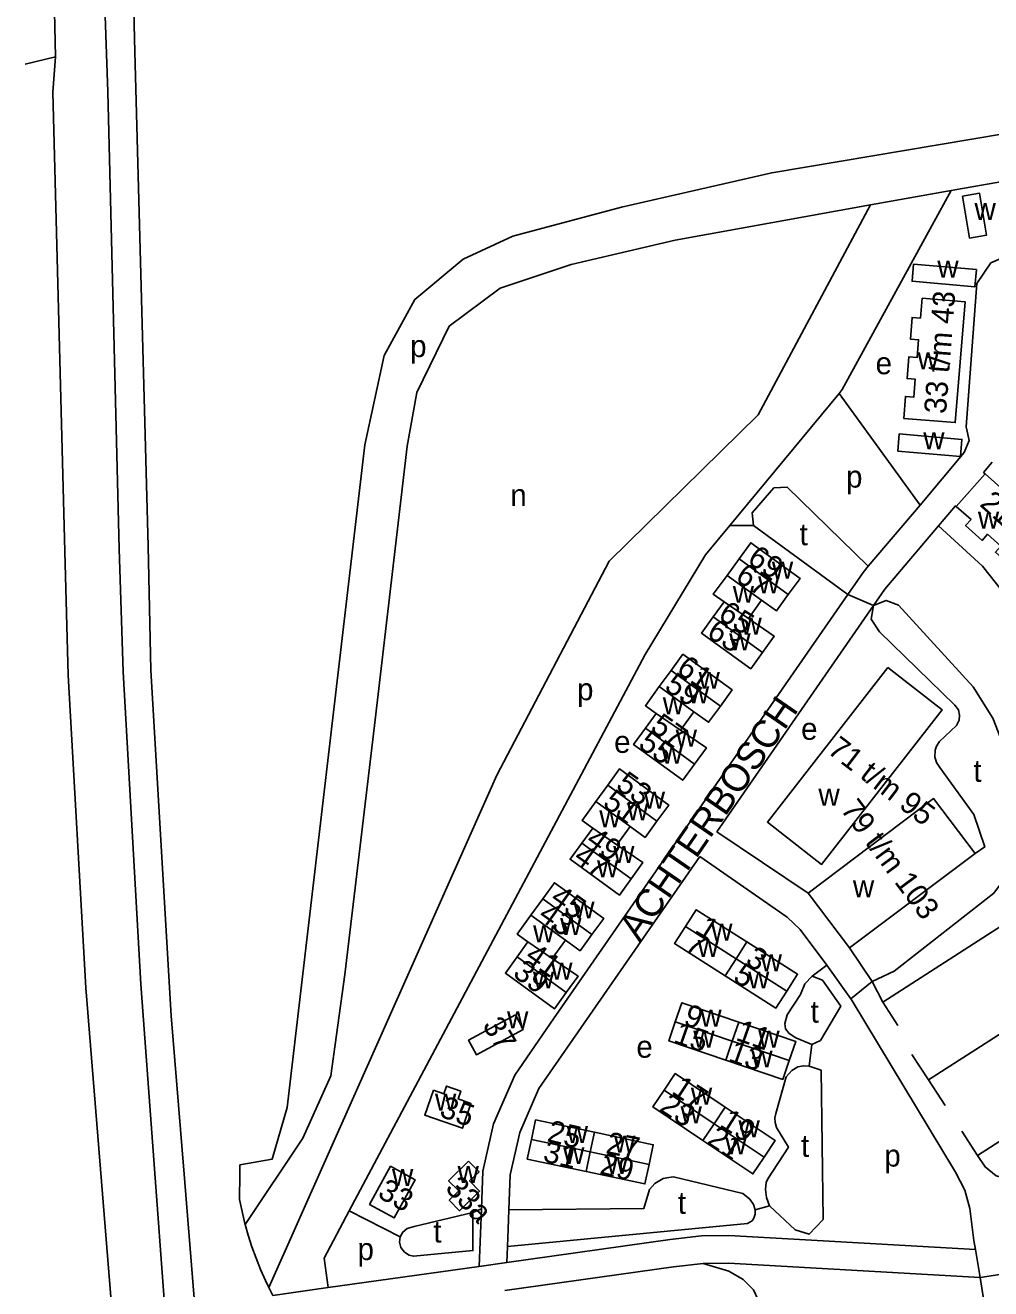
# Model space of a CAD drawing. Extents: x 159441 to 162086, y 388175 to 389787.
# Drawn here: x 159441.2 to 159616.2, y 389297.7 to 389526.7 of the extents above; entities that cross this region are included whole.
import ezdxf

# ---------------------------------------------------------------- set-up
doc = ezdxf.new("R2010")
doc.units = 0
for name, color, linetype in [('BLT_Basislijn', 7, 'Continuous'), ('BLT_Bebouwing', 7, 'Continuous'), ('BLT_Centroide', 7, 'Continuous'), ('BLT_Huisnummer', 7, 'Continuous'), ('BLT_Huisnummer_reeks', 7, 'Continuous'), ('BLT_Huisnummer_zonder_bebouwing', 7, 'Continuous'), ('BLT_Onderverdeling_panden', 7, 'Continuous'), ('BLT_Straatnaam', 7, 'Continuous'), ('BLT_Vlakafsluiter', 7, 'Continuous')]:
    doc.layers.add(name, color=color, linetype=linetype)

msp = doc.modelspace()

# ---------------------------------------------------------------- linework, layer by layer
at = {"layer": 'BLT_Basislijn'}
for p, q in [((159456.14, 389514.65), (159452.85, 389606.54)), ((159446.66, 389521.01), (159446.27, 389536.45)), ((159460.69, 389535.06), (159461.02, 389521.94)), ((159441.17, 389519.69), (159446.66, 389521.01)), ((159446.66, 389521.01), (159446.14, 389514.61)), ((159609.01, 389496.76), (159648.67, 389503.75)), ((159594.35, 389494.18), (159609.01, 389496.76)), ((159605.56, 389490.52), (159609.01, 389496.76)), ((159588.67, 389460.02), (159568.85, 389436.06)), ((159603.34, 389439.78), (159588.67, 389460.02)), ((159603.34, 389439.78), (159611.36, 389449.27)), ((159593.96, 389428.68), (159603.34, 389439.78)), ((159573.18, 389436.06), (159568.85, 389436.06)), ((159596.99, 389424.51), (159606.68, 389435.99)), ((159593.01, 389427.56), (159593.96, 389428.68)), ((159593.01, 389427.56), (159592.06, 389426.18)), ((159590.25, 389423.57), (159536.39, 389345.83)), ((159596.99, 389424.51), (159594.94, 389421.56)), ((159594.94, 389421.56), (159593.3, 389419.2)), ((159593.3, 389419.2), (159566.54, 389380.56)), ((159463.9, 389409.86), (159467.58, 389347.17)), ((159452.13, 389352.28), (159448.93, 389408.92)), ((159462.11, 389352.93), (159458.91, 389409.55)), ((159583.05, 389369.44), (159566.54, 389380.56)), ((159579.24, 389365.07), (159563.41, 389376.04)), ((159590.54, 389359.5), (159594.68, 389353.4)), ((159583.78, 389354.37), (159586.47, 389356.4)), ((159590.8, 389350.29), (159586.47, 389356.4)), ((159467.02, 389286.95), (159462.11, 389352.93)), ((159594.68, 389353.4), (159590.8, 389350.29)), ((159594.68, 389353.4), (159596.59, 389349.69)), ((159633.03, 389353.66), (159604.89, 389335.56)), ((159462.71, 389221.52), (159452.13, 389352.28)), ((159591.07, 389349.9), (159590.8, 389350.29)), ((159585.29, 389342.74), (159589.01, 389348.93)), ((159596.59, 389349.69), (159599.3, 389345.44)), ((159467.58, 389347.17), (159469.94, 389318.49)), ((159583.72, 389341.97), (159583.26, 389338.05)), ((159583.72, 389341.97), (159585.29, 389342.74)), ((159601.88, 389340.18), (159604.89, 389335.56)), ((159583.26, 389338.05), (159585.4, 389337.35)), ((159585.4, 389337.35), (159585.76, 389310.26)), ((159604.89, 389335.56), (159607.9, 389330.93)), ((159610.91, 389326.3), (159613.79, 389321.86)), ((159469.94, 389318.49), (159471.92, 389294.52)), ((159480.05, 389318.49), (159480.01, 389313.88)), ((159480.06, 389320.16), (159480.05, 389318.49)), ((159509.13, 389307.16), (159499.88, 389311.82)), ((159522.27, 389311.54), (159523.83, 389312.19)), ((159523.83, 389312.19), (159523.65, 389307.74)), ((159528.83, 389312.03), (159528.69, 389308.55)), ((159576.08, 389312.78), (159573.44, 389312.04)), ((159523.65, 389307.74), (159523.41, 389301.78)), ((159528.69, 389308.55), (159528.56, 389305.4)), ((159528.56, 389305.4), (159528.45, 389302.49)), ((159585.8, 389306.38), (159613.39, 389304.83)), ((159613.12, 389306.48), (159613.39, 389304.83)), ((159613.39, 389304.83), (159614.22, 389299.77)), ((159496.06, 389297.92), (159523.41, 389301.78)), ((159614.22, 389299.77), (159618.03, 389276.62)), ((159486.01, 389296.51), (159485.33, 389297.92)), ((159486.01, 389296.51), (159496.06, 389297.92))]:
    msp.add_line(p, q, dxfattribs=at)
for points in [[(159461.02, 389521.94), (159463.46, 389432.31), (159463.9, 389409.86)], [(159729.75, 389522.45), (159725.62, 389523.47), (159714.9, 389522.58), (159699.07, 389520.6), (159636.81, 389510.14), (159576.46, 389500), (159549.25, 389493.78), (159529.53, 389488.52), (159520.54, 389484.36), (159511.76, 389477.05), (159506.19, 389466.88), (159502.71, 389450.67), (159488.62, 389330.56), (159485.93, 389321.22), (159480.06, 389320.16)], [(159446.14, 389514.61), (159448.31, 389431.33), (159448.93, 389408.92)], [(159456.14, 389514.65), (159458.16, 389431.85), (159458.91, 389409.55)], [(159481.02, 389309.39), (159491.45, 389324.99), (159496.53, 389336.34), (159499.1, 389354.67), (159504.47, 389399.83), (159510.39, 389450.42), (159512.15, 389460.19), (159517.98, 389472.19), (159527.22, 389479.07), (159540.14, 389483.37), (159558.97, 389487.77), (159594.35, 389494.18)], [(159485.33, 389297.92), (159526.65, 389390.84), (159546.97, 389429.61), (159574, 389456.12), (159594.35, 389494.18)], [(159605.56, 389490.52), (159589.25, 389460.72), (159588.67, 389460.02)], [(159660.46, 389461.36), (159661.13, 389462.39), (159661.9, 389464.88), (159662.2, 389467.92), (159661.42, 389471.02), (159655.15, 389484.76), (159653.87, 389486.95), (159651.67, 389488.78), (159648.94, 389489.53), (159646.1, 389489.53), (159620.2, 389485.41), (159616.16, 389483.7)], [(159616.16, 389483.7), (159613.65, 389479.94), (159611.71, 389453.94), (159612.24, 389451.45), (159611.36, 389449.27)], [(159615.17, 389445.41), (159614.87, 389445.68), (159616.44, 389447.53)], [(159606.68, 389435.99), (159609.78, 389439.65), (159609.91, 389439.53)], [(159568.85, 389436.06), (159564.47, 389430.76), (159553.55, 389412.68), (159499.88, 389311.82)], [(159644.07, 389397.53), (159635.64, 389391.55), (159633.35, 389390.44), (159631.68, 389393.13), (159624.63, 389412.89), (159620.63, 389421.13), (159614.68, 389428.68), (159606.68, 389435.99)], [(159594.94, 389421.56), (159594.49, 389419.09), (159596.01, 389416.82), (159609.64, 389403.52), (159610.29, 389402.63), (159610.48, 389401.71), (159610.43, 389400.79), (159609.94, 389399.84), (159606.86, 389396.92), (159606.3, 389396.08), (159606.11, 389395.32), (159606.03, 389394.11), (159606.34, 389393.11), (159606.95, 389392.21), (159613.1, 389383.71), (159615.08, 389377.8), (159613.31, 389376.63)], [(159623.09, 389383.38), (159622.3, 389386.4), (159616.55, 389401.14), (159612.97, 389406.85), (159599.47, 389421.64), (159597.18, 389422.5), (159594.94, 389421.56)], [(159594.68, 389353.4), (159598.63, 389355.28), (159616.73, 389369.44), (159618.83, 389372.29), (159622.61, 389380.94), (159623.09, 389383.38)], [(159563.41, 389376.04), (159534.28, 389334), (159530.78, 389326.04), (159529.08, 389318.37), (159528.83, 389312.03)], [(159596.59, 389349.69), (159624.19, 389367.42), (159633.03, 389353.66)], [(159586.47, 389356.4), (159581.62, 389362.83), (159579.24, 389365.07)], [(159583.78, 389354.37), (159582.45, 389352.96), (159581.67, 389351.04), (159579.28, 389347.36), (159578.86, 389345.82), (159578.99, 389344.82), (159579.6, 389344.01), (159580.86, 389343.23), (159583.72, 389341.97)], [(159589.01, 389348.93), (159585.65, 389353.63), (159583.78, 389354.37)], [(159633.03, 389353.66), (159635.54, 389349.74), (159640.23, 389352.48), (159643.75, 389346.45), (159639.52, 389343.56), (159641.87, 389339.9), (159613.79, 389321.86)], [(159591.07, 389349.9), (159609.8, 389318.84), (159611.45, 389315.58), (159612.35, 389312.24), (159613.12, 389306.48)], [(159536.39, 389345.83), (159529.9, 389336.45), (159526.01, 389327.6), (159524.1, 389319.01), (159523.83, 389312.19)], [(159576.08, 389312.78), (159575.49, 389314.27), (159575.33, 389315.73), (159575.47, 389316.96), (159575.75, 389317.65), (159579.48, 389323.39), (159577.34, 389326.92), (159577.06, 389327.88), (159577.02, 389328.68), (159577.22, 389329.5), (159579.07, 389336.14), (159580.08, 389337.29), (159581.19, 389337.95), (159582.26, 389338.14), (159583.26, 389338.05)], [(159613.79, 389321.86), (159615.14, 389319.8), (159617.17, 389318.2), (159619.17, 389317.65), (159621.07, 389318.1)], [(159528.83, 389312.03), (159553.26, 389312.24), (159554.32, 389315.71), (159555.28, 389316.8), (159556.79, 389317.68), (159557.84, 389317.91), (159558.67, 389318), (159571.24, 389314.98), (159572.51, 389313.94), (159573.17, 389312.97), (159573.44, 389312.04)], [(159480.01, 389313.88), (159480.45, 389311.71), (159480.97, 389309.57), (159481.02, 389309.39)], [(159499.88, 389311.82), (159495.33, 389303.28), (159496.06, 389297.92)], [(159522.27, 389311.54), (159522.31, 389304.65), (159511.53, 389303.62), (159510.74, 389303.82), (159509.9, 389304.37), (159509.24, 389305.19), (159508.97, 389306.16), (159509.13, 389307.16)], [(159509.13, 389307.16), (159509.61, 389307.99), (159510.39, 389308.62), (159511.68, 389309.01), (159522.27, 389311.54)], [(159573.44, 389312.04), (159573.46, 389311.23), (159573.24, 389310.53), (159572.89, 389310.04), (159572.08, 389309.54), (159528.56, 389305.4)], [(159585.76, 389310.26), (159583.27, 389307.59), (159580.72, 389308.38), (159576.08, 389312.78)], [(159481.02, 389309.39), (159481.56, 389307.44), (159482.24, 389305.34), (159482.99, 389303.26), (159483.81, 389301.21), (159484.71, 389299.2), (159485.33, 389297.92)], [(159528.45, 389302.49), (159558.04, 389306.66), (159563.74, 389307.29), (159568.71, 389307.35), (159585.8, 389306.38)], [(159528.09, 389297.39), (159558.67, 389301.69), (159564.04, 389302.3)], [(159564.04, 389302.3), (159568.6, 389302.35), (159614.22, 389299.77)], [(159588.03, 389259.71), (159576.49, 389288.62), (159574.22, 389295.17), (159573.15, 389297.51), (159571.28, 389299.4), (159568.69, 389300.91), (159564.04, 389302.3)]]:
    msp.add_lwpolyline(points, dxfattribs=at)
at = {"layer": 'BLT_Bebouwing'}
for p, q in [((159609.91, 389439.53), (159615.17, 389445.41)), ((159573.18, 389436.06), (159590.25, 389423.57)), ((159568.36, 389427.01), (159570.54, 389430.01)), ((159592.06, 389426.18), (159590.25, 389423.57)), ((159565.87, 389419.52), (159567.82, 389422.2)), ((159574.63, 389422.54), (159572.24, 389419.19)), ((159558.23, 389409.79), (159556.09, 389406.86)), ((159555.51, 389401.98), (159553.59, 389399.33)), ((159559.92, 389398.97), (159562.35, 389402.32)), ((159546.73, 389389), (159544.58, 389386.03)), ((159544.03, 389381.19), (159542.07, 389378.5)), ((159548.41, 389378.18), (159550.82, 389381.5)), ((159590.54, 389359.5), (159613.31, 389376.63)), ((159534.97, 389368.39), (159532.81, 389365.42)), ((159583.05, 389369.44), (159590.54, 389359.5)), ((159530.32, 389357.9), (159532.27, 389360.59)), ((159536.66, 389357.58), (159539.07, 389360.91))]:
    msp.add_line(p, q, dxfattribs=at)
for points in [[(159611.07, 389495.77), (159614.15, 389496.28), (159615.37, 389488.67), (159612.29, 389488.17)], [(159602.16, 389483.44), (159613.57, 389482.45), (159613.3, 389479.35), (159601.9, 389480.35)], [(159599.55, 389452.65), (159610.95, 389451.67), (159610.69, 389448.58), (159599.3, 389449.55)], [(159597.53, 389410.33), (159607.34, 389402.68), (159585.49, 389374.64), (159575.67, 389382.31)], [(159530, 389347.36), (159521.51, 389342.76), (159522.95, 389340.15), (159531.42, 389344.73)], [(159515.18, 389333.7), (159517.02, 389333.04), (159517.52, 389334.45), (159520.11, 389333.53), (159519.61, 389332.12), (159521.94, 389331.29), (159520.39, 389326.82), (159513.58, 389329.21)], [(159521.52, 389320.87), (159523.42, 389318.94), (159521.69, 389317.27), (159523.52, 389315.41), (159519.88, 389311.85), (159518, 389313.78), (159519.73, 389315.45), (159517.89, 389317.3)], [(159507.34, 389319.92), (159503.56, 389313.02), (159508.04, 389310.57), (159511.81, 389317.47)]]:
    msp.add_lwpolyline(points, close=True, dxfattribs=at)
for points in [[(159603.72, 389477.25), (159611.5, 389476.63), (159609.74, 389454.71), (159600.38, 389455.46), (159600.71, 389459.46), (159602.21, 389459.32), (159602.49, 389462.56), (159600.99, 389462.68), (159601.31, 389466.62), (159602.82, 389466.5), (159603.09, 389469.72), (159601.59, 389469.85), (159601.91, 389473.77), (159603.43, 389473.65), (159603.72, 389477.25)], [(159615.17, 389445.41), (159631.6, 389430.76), (159625.33, 389423.78), (159622.38, 389426.43), (159623.37, 389427.53), (159620.99, 389429.66), (159619.99, 389428.55), (159617, 389431.22), (159617.99, 389432.33), (159615.58, 389434.49), (159614.58, 389433.37), (159611.59, 389436.05), (159612.59, 389437.14), (159609.91, 389439.53)], [(159593.96, 389428.68), (159579.29, 389443.04), (159576.87, 389442.89), (159572.94, 389438.39), (159573.18, 389436.06)], [(159570.54, 389430.01), (159572.66, 389432.94), (159581.59, 389426.46), (159579.46, 389423.53)], [(159567.82, 389422.2), (159565.88, 389423.61), (159568.36, 389427.01)], [(159579.46, 389423.53), (159577.34, 389420.61), (159574.63, 389422.54)], [(159574.79, 389413.04), (159572.65, 389410.09), (159563.73, 389416.57), (159565.87, 389419.52)], [(159572.24, 389419.19), (159576.93, 389415.98), (159574.79, 389413.04)], [(159567.15, 389403.32), (159569.28, 389406.25), (159560.37, 389412.74), (159558.23, 389409.79)], [(159556.09, 389406.86), (159553.58, 389403.39), (159555.51, 389401.98)], [(159562.35, 389402.32), (159565.02, 389400.39), (159567.15, 389403.32)], [(159562.49, 389392.81), (159560.34, 389389.88), (159551.43, 389396.36), (159553.59, 389399.33)], [(159559.92, 389398.97), (159564.64, 389395.75), (159562.49, 389392.81)], [(159555.66, 389382.47), (159557.8, 389385.4), (159548.87, 389391.93), (159546.73, 389389)], [(159544.58, 389386.03), (159542.08, 389382.6), (159544.03, 389381.19)], [(159613.31, 389376.63), (159605.81, 389386.58), (159583.05, 389369.44)], [(159550.82, 389381.5), (159553.52, 389379.54), (159555.66, 389382.47)], [(159550.99, 389372.02), (159548.85, 389369.08), (159539.93, 389375.56), (159542.07, 389378.5)], [(159548.41, 389378.18), (159553.12, 389374.96), (159550.99, 389372.02)], [(159534.97, 389368.39), (159537.09, 389371.32), (159546.01, 389364.85), (159543.88, 389361.92)], [(159571.94, 389360.58), (159562.75, 389366.43), (159560.81, 389363.37)], [(159532.81, 389365.42), (159530.33, 389362), (159532.27, 389360.59)], [(159543.88, 389361.92), (159541.74, 389358.98), (159539.07, 389360.91)], [(159560.81, 389363.37), (159558.86, 389360.29), (159568.04, 389354.44)], [(159579.18, 389351.66), (159581.14, 389354.72), (159571.94, 389360.58)], [(159539.23, 389351.42), (159537.1, 389348.48), (159528.18, 389354.95), (159530.32, 389357.9)], [(159536.66, 389357.58), (159541.37, 389354.36), (159539.23, 389351.42)], [(159568.04, 389354.44), (159577.23, 389348.59), (159579.18, 389351.66)], [(159570.48, 389346.05), (159560.16, 389349.55), (159558.99, 389346.08)], [(159558.99, 389346.08), (159557.83, 389342.63), (159568.14, 389339.14)], [(159579.64, 389339.11), (159580.81, 389342.56), (159570.48, 389346.05)], [(159568.14, 389339.14), (159578.47, 389335.65), (159579.64, 389339.11)], [(159568.05, 389330.66), (159558.99, 389336.73), (159556.96, 389333.7)], [(159556.96, 389333.7), (159554.93, 389330.69), (159563.99, 389324.61)], [(159575.08, 389321.56), (159577.11, 389324.58), (159568.05, 389330.66)], [(159544.33, 389326.08), (159533.66, 389328.33), (159532.91, 389324.77)], [(159554.24, 389320.27), (159554.99, 389323.83), (159544.33, 389326.08)], [(159532.91, 389324.77), (159532.16, 389321.21), (159542.82, 389318.96)], [(159563.99, 389324.61), (159573.06, 389318.53), (159575.08, 389321.56)], [(159542.82, 389318.96), (159553.49, 389316.71), (159554.24, 389320.27)]]:
    msp.add_lwpolyline(points, dxfattribs=at)
at = {"layer": 'BLT_Onderverdeling_panden'}
for p, q in [((159570.54, 389430.01), (159579.46, 389423.53)), ((159568.36, 389427.01), (159574.63, 389422.54)), ((159567.82, 389422.2), (159572.24, 389419.19)), ((159565.87, 389419.52), (159574.79, 389413.04)), ((159558.23, 389409.79), (159567.15, 389403.32)), ((159556.09, 389406.86), (159562.35, 389402.32)), ((159555.51, 389401.98), (159559.92, 389398.97)), ((159553.59, 389399.33), (159562.49, 389392.81)), ((159546.73, 389389), (159555.66, 389382.47)), ((159544.58, 389386.03), (159550.82, 389381.5)), ((159544.03, 389381.19), (159548.41, 389378.18)), ((159542.07, 389378.5), (159550.99, 389372.02)), ((159534.97, 389368.39), (159543.88, 389361.92)), ((159532.81, 389365.42), (159539.07, 389360.91)), ((159560.81, 389363.37), (159569.99, 389357.51)), ((159532.27, 389360.59), (159536.66, 389357.58)), ((159569.99, 389357.51), (159571.94, 389360.58)), ((159530.32, 389357.9), (159539.23, 389351.42)), ((159569.99, 389357.51), (159568.04, 389354.44)), ((159569.99, 389357.51), (159579.18, 389351.66)), ((159569.31, 389342.6), (159558.99, 389346.08)), ((159569.31, 389342.6), (159570.48, 389346.05)), ((159569.31, 389342.6), (159568.14, 389339.14)), ((159569.31, 389342.6), (159579.64, 389339.11)), ((159556.96, 389333.7), (159566.02, 389327.63)), ((159568.05, 389330.66), (159566.02, 389327.63)), ((159566.02, 389327.63), (159563.99, 389324.61)), ((159566.02, 389327.63), (159575.08, 389321.56)), ((159543.58, 389322.52), (159544.33, 389326.08)), ((159532.91, 389324.77), (159543.58, 389322.52)), ((159543.58, 389322.52), (159542.82, 389318.96)), ((159543.58, 389322.52), (159554.24, 389320.27))]:
    msp.add_line(p, q, dxfattribs=at)
at = {"layer": 'BLT_Vlakafsluiter'}
for p, q in [((159590.25, 389423.57), (159594.94, 389421.56)), ((159523.41, 389301.78), (159528.45, 389302.49)), ((159614.22, 389299.77), (159622.13, 389300.99))]:
    msp.add_line(p, q, dxfattribs=at)

# ---------------------------------------------------------------- texts
at = {"layer": 'BLT_Centroide'}
for s, p in [('w', (159613.22, 389491.42)), ('w', (159606.48, 389480.99)), ('p', (159510.93, 389466.59)), ('w', (159602.87, 389464.39)), ('e', (159595.29, 389463.48)), ('w', (159603.93, 389449.89)), ('p', (159589.94, 389442.93)), ('n', (159529.08, 389439.57)), ('w', (159613.83, 389435.52)), ('t', (159581.51, 389432.48)), ('w', (159576.49, 389426.44)), ('w', (159574, 389423.76)), ('w', (159569.4, 389422.05)), ('w', (159570.8, 389416.29)), ('w', (159568.76, 389413.42)), ('p', (159541.18, 389404.39)), ('w', (159563.2, 389406.46)), ('w', (159561.27, 389403.82)), ('w', (159556.71, 389401.86)), ('w', (159559.06, 389396)), ('e', (159581.79, 389397.22)), ('e', (159547.9, 389394.85)), ('w', (159556.46, 389392.88)), ('t', (159613.02, 389389.6)), ('w', (159553.26, 389384.76)), ('w', (159584.93, 389385.27)), ('w', (159545.2, 389381.38)), ('w', (159550.25, 389382.65)), ('w', (159547.72, 389374.92)), ('w', (159544.79, 389372.32)), ('w', (159591.18, 389368.66)), ('w', (159540.49, 389364.84)), ('w', (159538.11, 389361.83)), ('w', (159565.49, 389360.83)), ('w', (159533.21, 389360.53)), ('w', (159563.01, 389357.88)), ('w', (159574.46, 389355.27)), ('w', (159533.17, 389352.15)), ('w', (159536.48, 389353.73)), ('w', (159572.17, 389352.15)), ('w', (159528.49, 389344.92)), ('w', (159563.52, 389345.22)), ('t', (159583.5, 389345.95)), ('w', (159562.25, 389341.42)), ('w', (159574.04, 389341.42)), ('e', (159551.93, 389339.6)), ('w', (159572.77, 389337.83)), ('w', (159561.81, 389331.08)), ('w', (159515.43, 389330)), ('w', (159559.94, 389327.71)), ('w', (159539.31, 389324.14)), ('w', (159570.44, 389325.16)), ('w', (159547.88, 389322.39)), ('w', (159568.06, 389322.06)), ('t', (159581.77, 389321.62)), ('w', (159538.66, 389320.31)), ('p', (159596.87, 389319.86)), ('w', (159546.52, 389318.55)), ('w', (159507.63, 389316.33)), ('w', (159519.52, 389316.9)), ('t', (159559.44, 389311.29)), ('t', (159515.13, 389306.09)), ('p', (159501.39, 389302.92))]:
    msp.add_text(s, height=4, dxfattribs=at).set_placement(p)
at = {"layer": 'BLT_Huisnummer'}
for s, rotation, p in [('69', 326.6171, (159571.83, 389429.4)), ('67', 326.6171, (159569.66, 389426.2)), ('65', 327.6171, (159566.54, 389419.28)), ('63', 327.6171, (159564.48, 389416.04)), ('61', 325.6171, (159558.98, 389409.5)), ('59', 325.6171, (159556.81, 389406.39)), ('57', 324.6171, (159554.25, 389399.03)), ('55', 324.6171, (159552.06, 389395.97)), ('53', 324.6171, (159547.99, 389388.51)), ('51', 323.6171, (159545.63, 389385.31)), ('49', 323.6171, (159542.55, 389378.48)), ('47', 324.6171, (159540.32, 389375.38)), ('45', 324.6171, (159536.09, 389367.93)), ('43', 324.6171, (159533.92, 389364.88)), ('1', 327.6171, (159562.68, 389362.18)), ('7', 328.6171, (159560.55, 389359.36)), ('41', 324.6171, (159531.52, 389357.44)), ('3', 327.6171, (159571.48, 389356.7)), ('39', 323.6171, (159529.34, 389354.49)), ('5', 327.6171, (159569.25, 389353.66)), ('9', 340.6171, (159560.28, 389345.67)), ('37', 300.6171, (159523.94, 389345.52)), ('15', 340.6171, (159558.47, 389342.44)), ('11', 340.6171, (159569.76, 389342.85)), ('13', 340.6171, (159568.4, 389339.08)), ('17', 326.6171, (159558.12, 389333.23)), ('23', 326.6171, (159555.9, 389330.11)), ('19', 327.6171, (159566.82, 389327.23)), ('25', 346.6171, (159535.58, 389324.47)), ('27', 348.6171, (159546.23, 389322.32)), ('21', 326.6171, (159564.52, 389324.16)), ('31', 346.6171, (159534.83, 389320.84)), ('29', 346.6171, (159545.12, 389318.61)), ('33', 330.6171, (159504.83, 389314.42))]:
    msp.add_text(s, height=4, rotation=rotation, dxfattribs=at).set_placement(p)
at = {"layer": 'BLT_Huisnummer_reeks'}
for s, rotation, p in [('33 t/m 43', 85.6171, (159608.05, 389456.21)), ('21 t/m 31', 318.1171, (159613.99, 389439.75)), ('71 t/m 95', 322.6171, (159586.35, 389394.97)), ('79 t/m 103', 306.6171, (159588.82, 389384.57))]:
    msp.add_text(s, height=4, rotation=rotation, dxfattribs=at).set_placement(p)
at = {"layer": 'BLT_Huisnummer_zonder_bebouwing'}
for s, rotation, p in [('35', 340.6171, (159516.04, 389329)), ('33a', 313.6171, (159517.11, 389315.79))]:
    msp.add_text(s, height=4, rotation=rotation, dxfattribs=at).set_placement(p)
at = {"layer": 'BLT_Straatnaam'}
msp.add_text('ACHTERBOSCH', height=5, rotation=55.5004, dxfattribs=at).set_placement((159552.44, 389360.51))

doc.saveas('drawing.dxf')
